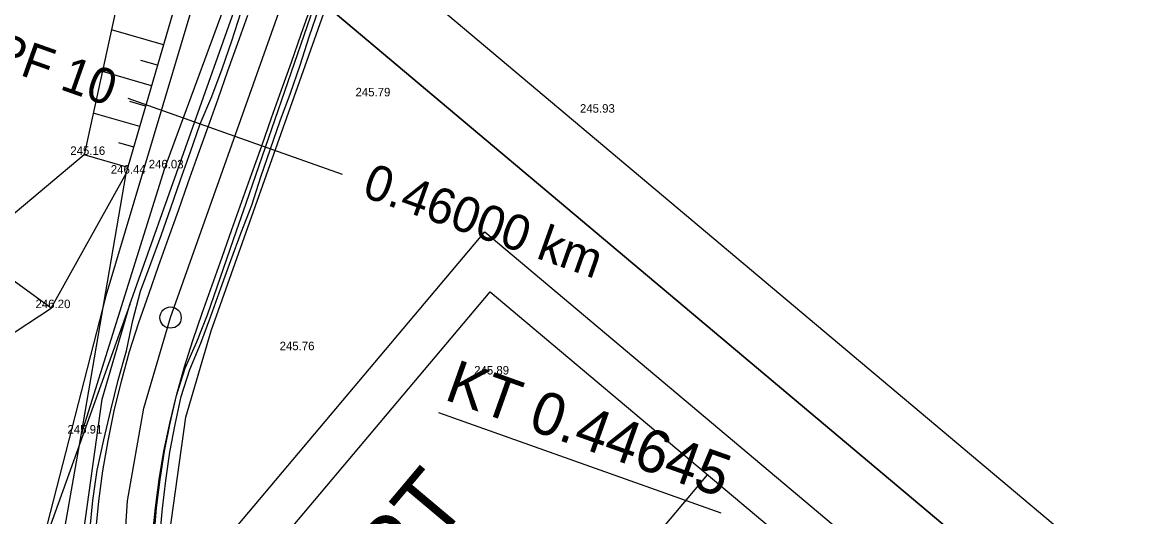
# Model space of a CAD drawing. Extents: x -555887 to -552101, y -1100251 to -1096546.
# Drawn here: x -554212 to -554133.1, y -1096937 to -1096902.3 of the extents above; entities that cross this region are included whole.
import ezdxf

# ---------------------------------------------------------------- set-up
doc = ezdxf.new("R2010")
doc.units = 0
for name, color, linetype in [('PARCELY_cesty', 7, 'Continuous'), ('PARCELY_VHO', 7, 'Continuous'), ('POLYGONY_SITUACE_PF', 7, 'Continuous'), ('POLYGONY_SITUACE_PF_POPISY', 7, 'Continuous'), ('POLYGONY_SITUACE_PO', 7, 'Continuous'), ('ram_VC2', 7, 'Continuous'), ('Výškopis', 7, 'Continuous'), ('ZSST', 7, 'Continuous')]:
    doc.layers.add(name, color=color, linetype=linetype)

msp = doc.modelspace()

# ---------------------------------------------------------------- linework, layer by layer
msp.add_line((-554182.74, -1096929.72), (-554162.862, -1096936.774))
at = {"layer": 'PARCELY_cesty'}
msp.add_line((-554204.443, -1096922.105), (-554210.92, -1096940.13), dxfattribs=at)
for points in [[(-554179.848, -1097011.434), (-554188.548, -1096997.769), (-554194.143, -1096986.978), (-554202.26, -1096969.466), (-554205.738, -1096959.672), (-554207.73, -1096949.505), (-554207.83, -1096939.06), (-554206.4, -1096928.769), (-554204.443, -1096922.105), (-554188.79, -1096877.98), (-554188.448, -1096871.476), (-554181.649, -1096851.898), (-554177.76, -1096846.91), (-554174.9, -1096838.86)], [(-554115.449, -1097149.447), (-554124.686, -1097127.011), (-554128.784, -1097114.843), (-554130.72, -1097105.514), (-554131.844, -1097095.954), (-554133.35, -1097067.01), (-554134.24, -1097060.44), (-554136.626, -1097054.868), (-554142.446, -1097045.834), (-554167.763, -1097017.307), (-554174.929, -1097007.988), (-554183.344, -1096994.771), (-554188.755, -1096984.334), (-554196.699, -1096967.196), (-554199.935, -1096958.083), (-554201.735, -1096948.894), (-554201.826, -1096939.447), (-554200.518, -1096930.034), (-554198.733, -1096923.955), (-554169.26, -1096840.86), (-554168.999, -1096840.134)]]:
    msp.add_lwpolyline(points, dxfattribs=at)
at = {"layer": 'PARCELY_VHO'}
msp.add_lwpolyline([(-554093.55, -1096750.72), (-554107.61, -1096766.97), (-554183.58, -1096830.32), (-554190.17, -1096868.02), (-554206.15, -1096921.51), (-554210.92, -1096940.13), (-554208.99, -1096958.65), (-554201.43, -1096978.3), (-554189.25, -1096999.78), (-554172.82, -1097024.19), (-554153.8, -1097046.73), (-554145.73, -1097061.02), (-554142.77, -1097083.92), (-554141.5, -1097107.04), (-554133.09, -1097133.96)], dxfattribs=at)
at = {"layer": 'POLYGONY_SITUACE_PF'}
for p, q in [((-554204.596, -1096907.589), (-554197.057, -1096910.265)), ((-554197.057, -1096910.265), (-554189.518, -1096912.941))]:
    msp.add_line(p, q, dxfattribs=at)
at = {"layer": 'POLYGONY_SITUACE_PO'}
for p, q in [((-554201.588, -1096923.03), (-554171.938, -1096839.49)), ((-554192.385, -1096903.08), (-554191.688, -1096901.117)), ((-554192.182, -1096903.153), (-554191.501, -1096901.183)), ((-554197.271, -1096903.557), (-554196.642, -1096901.57)), ((-554196.852, -1096903.706), (-554196.155, -1096901.742)), ((-554191.826, -1096903.279), (-554191.155, -1096901.306)), ((-554197.944, -1096905.529), (-554197.271, -1096903.557)), ((-554193.082, -1096905.044), (-554192.385, -1096903.08)), ((-554192.862, -1096905.122), (-554192.182, -1096903.153)), ((-554192.458, -1096905.265), (-554191.826, -1096903.279)), ((-554197.548, -1096905.669), (-554196.852, -1096903.706)), ((-554193.779, -1096907.007), (-554193.082, -1096905.044)), ((-554193.542, -1096907.091), (-554192.862, -1096905.122)), ((-554198.687, -1096907.476), (-554197.944, -1096905.529)), ((-554198.245, -1096907.633), (-554197.548, -1096905.669)), ((-554193.151, -1096907.23), (-554192.458, -1096905.265)), ((-554199.501, -1096909.398), (-554198.687, -1096907.476)), ((-554194.476, -1096908.97), (-554193.779, -1096907.007)), ((-554194.223, -1096909.06), (-554193.542, -1096907.091)), ((-554193.879, -1096909.182), (-554193.151, -1096907.23)), ((-554198.942, -1096909.596), (-554198.245, -1096907.633)), ((-554195.172, -1096910.934), (-554194.476, -1096908.97)), ((-554194.903, -1096911.029), (-554194.223, -1096909.06)), ((-554200.177, -1096911.368), (-554199.501, -1096909.398)), ((-554199.639, -1096911.559), (-554198.942, -1096909.596)), ((-554194.555, -1096911.153), (-554193.879, -1096909.182)), ((-554200.885, -1096913.328), (-554200.177, -1096911.368)), ((-554195.869, -1096912.897), (-554195.172, -1096910.934)), ((-554195.583, -1096912.999), (-554194.903, -1096911.029)), ((-554195.24, -1096913.12), (-554194.555, -1096911.153)), ((-554200.336, -1096913.523), (-554199.639, -1096911.559)), ((-554196.566, -1096914.86), (-554195.869, -1096912.897)), ((-554196.263, -1096914.968), (-554195.583, -1096912.999)), ((-554201.562, -1096915.298), (-554200.885, -1096913.328)), ((-554201.033, -1096915.486), (-554200.336, -1096913.523)), ((-554195.864, -1096915.11), (-554195.24, -1096913.12)), ((-554202.252, -1096917.264), (-554201.562, -1096915.298)), ((-554197.263, -1096916.824), (-554196.566, -1096914.86)), ((-554196.944, -1096916.937), (-554196.263, -1096914.968)), ((-554196.621, -1096917.052), (-554195.864, -1096915.11)), ((-554201.729, -1096917.449), (-554201.033, -1096915.486)), ((-554197.96, -1096918.787), (-554197.263, -1096916.824)), ((-554197.624, -1096918.906), (-554196.944, -1096916.937)), ((-554202.976, -1096919.218), (-554202.252, -1096917.264)), ((-554202.426, -1096919.413), (-554201.729, -1096917.449)), ((-554197.343, -1096919.006), (-554196.621, -1096917.052)), ((-554203.699, -1096921.171), (-554202.976, -1096919.218)), ((-554198.657, -1096920.75), (-554197.96, -1096918.787)), ((-554198.304, -1096920.875), (-554197.624, -1096918.906)), ((-554198.054, -1096920.964), (-554197.343, -1096919.006)), ((-554203.123, -1096921.376), (-554202.426, -1096919.413)), ((-554199.353, -1096922.714), (-554198.657, -1096920.75)), ((-554198.985, -1096922.845), (-554198.304, -1096920.875)), ((-554204.242, -1096923.234), (-554203.699, -1096921.171)), ((-554203.816, -1096923.377), (-554203.123, -1096921.376)), ((-554198.755, -1096922.926), (-554198.054, -1096920.964)), ((-554204.684, -1096925.364), (-554204.242, -1096923.234)), ((-554203.459, -1096929.401), (-554201.588, -1096923.03)), ((-554200.023, -1096924.65), (-554199.353, -1096922.714)), ((-554199.742, -1096924.744), (-554198.985, -1096922.845)), ((-554199.449, -1096924.843), (-554198.755, -1096922.926)), ((-554204.467, -1096925.429), (-554203.816, -1096923.377)), ((-554200.633, -1096926.569), (-554200.023, -1096924.65)), ((-554200.548, -1096926.594), (-554199.742, -1096924.744)), ((-554200.219, -1096926.692), (-554199.449, -1096924.843)), ((-554205.27, -1096927.444), (-554204.684, -1096925.364)), ((-554205.043, -1096927.503), (-554204.467, -1096925.429)), ((-554201.172, -1096928.509), (-554200.633, -1096926.569)), ((-554201.161, -1096928.512), (-554200.548, -1096926.594)), ((-554200.828, -1096928.598), (-554200.219, -1096926.692)), ((-554205.788, -1096929.542), (-554205.27, -1096927.444)), ((-554205.548, -1096929.595), (-554205.043, -1096927.503)), ((-554201.644, -1096930.466), (-554201.172, -1096928.509)), ((-554201.614, -1096930.473), (-554201.161, -1096928.512)), ((-554201.259, -1096930.552), (-554200.828, -1096928.598)), ((-554206.276, -1096931.648), (-554205.788, -1096929.542)), ((-554205.982, -1096931.703), (-554205.548, -1096929.595)), ((-554204.615, -1096935.94), (-554203.459, -1096929.401)), ((-554202.051, -1096932.439), (-554201.644, -1096930.466)), ((-554202.001, -1096932.448), (-554201.614, -1096930.473)), ((-554201.629, -1096932.517), (-554201.259, -1096930.552)), ((-554206.75, -1096933.764), (-554206.276, -1096931.648)), ((-554206.341, -1096933.826), (-554205.982, -1096931.703)), ((-554202.386, -1096934.424), (-554202.051, -1096932.439)), ((-554202.317, -1096934.434), (-554202.001, -1096932.448)), ((-554201.925, -1096934.494), (-554201.629, -1096932.517)), ((-554207.056, -1096935.909), (-554206.75, -1096933.764)), ((-554206.626, -1096935.959), (-554206.341, -1096933.826)), ((-554202.653, -1096936.42), (-554202.386, -1096934.424)), ((-554202.564, -1096936.43), (-554202.317, -1096934.434)), ((-554202.15, -1096936.478), (-554201.925, -1096934.494)), ((-554207.256, -1096938.067), (-554207.056, -1096935.909)), ((-554205.041, -1096942.567), (-554204.615, -1096935.94)), ((-554206.835, -1096938.102), (-554206.626, -1096935.959)), ((-554202.848, -1096938.424), (-554202.653, -1096936.42)), ((-554202.739, -1096938.433), (-554202.564, -1096936.43)), ((-554202.332, -1096938.466), (-554202.15, -1096936.478))]:
    msp.add_line(p, q, dxfattribs=at)
msp.add_circle((-554201.588, -1096923.03), 0.75, dxfattribs=at)
at = {"layer": 'ram_VC2'}
msp.add_line((-554279.698, -1097071.818), (-554163.803, -1096934.092), dxfattribs=at)
for points in [[(-554114.88, -1096958.27), (-554342.128, -1096767.044), (-555018.181, -1097570.444), (-554790.933, -1097761.671)], [(-554121.925, -1096958.876), (-554341.521, -1096774.089), (-555011.135, -1097569.838), (-554791.539, -1097754.626)], [(-554299.227, -1097059.305), (-554179.469, -1096916.988), (-554128.97, -1096959.483), (-554248.728, -1097101.8)], [(-554295, -1097058.941), (-554179.106, -1096921.215), (-554133.197, -1096959.847), (-554249.092, -1097097.572)]]:
    msp.add_lwpolyline(points, close=True, dxfattribs=at)
for points in [[(-554114.88, -1096958.27), (-554342.128, -1096767.044), (-555018.181, -1097570.444), (-554790.933, -1097761.671), (-554114.88, -1096958.27)], [(-554791.539, -1097754.626), (-555011.135, -1097569.838), (-554341.521, -1096774.089), (-554121.925, -1096958.876), (-554791.539, -1097754.626)]]:
    msp.add_lwpolyline(points, dxfattribs=at)
at = {"layer": 'ZSST'}
for p, q in [((-554202.081, -1096903.83), (-554205.742, -1096902.765)), ((-554202.5, -1096905.27), (-554203.686, -1096904.925)), ((-554202.919, -1096906.711), (-554206.381, -1096905.703)), ((-554203.338, -1096908.151), (-554204.458, -1096907.825)), ((-554203.757, -1096909.591), (-554207.021, -1096908.642)), ((-554204.176, -1096911.031), (-554205.23, -1096910.725)), ((-554204.595, -1096912.472), (-554207.66, -1096911.58)), ((-554209.99, -1096922.37), (-554204.72, -1096912.9))]:
    msp.add_line(p, q, dxfattribs=at)
for points in [[(-554170.85, -1096833.24), (-554179.04, -1096845.27), (-554185.36, -1096859.55), (-554193.03, -1096883.86), (-554196.79, -1096898.33), (-554202.02, -1096912.53), (-554207.86, -1096931.2)], [(-554189.44, -1097009.07), (-554189.29, -1097003.58), (-554192.09, -1096996.42), (-554196.79, -1096989.85), (-554203.75, -1096978.28), (-554211.03, -1096961.03), (-554216.96, -1096944.48), (-554220.11, -1096936.16), (-554213.34, -1096924.57), (-554209.99, -1096922.37), (-554215.63, -1096918.27), (-554219.45, -1096911.72), (-554215.85, -1096907.48), (-554214.43, -1096900.67), (-554212.25, -1096888.64), (-554208.26, -1096873.22), (-554195.25, -1096867.45)], [(-554194.65, -1096867.38), (-554199.39, -1096880.25), (-554203.75, -1096893.61), (-554207.66, -1096911.58), (-554215.63, -1096918.27)], [(-554183.21, -1097006.5), (-554191.67, -1096991.83), (-554198.21, -1096980.78), (-554201.06, -1096974.23), (-554205.6, -1096961.82), (-554208.86, -1096949.13), (-554209.49, -1096940.5), (-554207.86, -1096931.2), (-554204.72, -1096912.9), (-554200.92, -1096899.84), (-554197.55, -1096886.55), (-554191.27, -1096867.82), (-554194.65, -1096867.38)]]:
    msp.add_lwpolyline(points, dxfattribs=at)

# ---------------------------------------------------------------- texts
msp.add_text('KT 0.44645', height=3, rotation=340.45955).set_placement((-554182.405, -1096928.777))
at = {"layer": 'POLYGONY_SITUACE_PF_POPISY'}
for s, p in [('PF 10', (-554214.355, -1096905.187)), ('0.46000 km', (-554188.2, -1096914.469))]:
    msp.add_text(s, height=2.5, rotation=340.45955, dxfattribs=at).set_placement(p)
at = {"layer": 'ram_VC2'}
msp.add_text('GEOCART', height=4.5, rotation=49.91975, dxfattribs=at).set_placement((-554199.672, -1096958.954))
at = {"layer": 'Výškopis'}
for s, p in [('245.79', (-554188.571, -1096907.46)), ('245.93', (-554172.778, -1096908.61)), ('245.16', (-554208.64, -1096911.58)), ('246.03', (-554203.122, -1096912.53)), ('246.44', (-554205.789, -1096912.9)), ('246.20', (-554211.088, -1096922.37)), ('245.76', (-554193.911, -1096925.33)), ('245.89', (-554180.22, -1096927.04)), ('245.91', (-554208.84, -1096931.2))]:
    msp.add_text(s, height=0.6, dxfattribs=at).set_placement(p)

doc.saveas('drawing.dxf')
